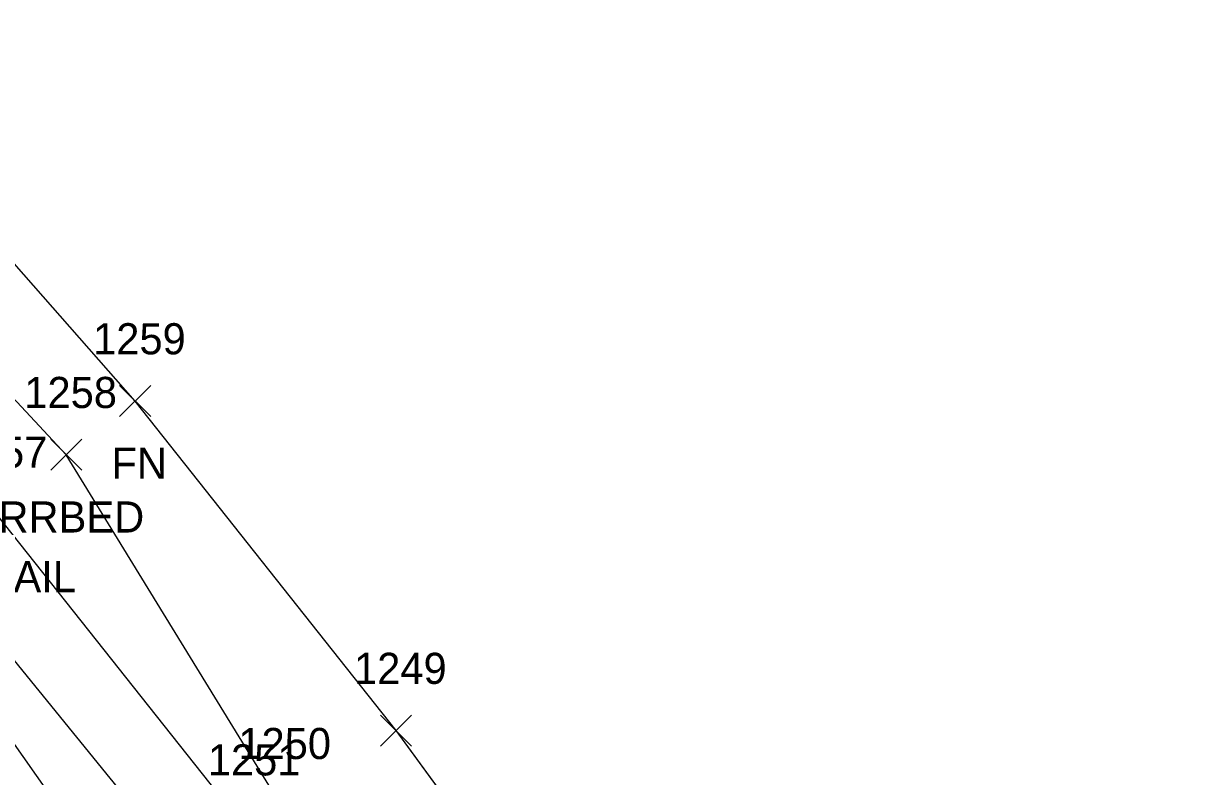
# Model space of a CAD drawing. Extents: x 1715662 to 1717487, y 887396 to 890004.
# Drawn here: x 1716350.8 to 1716426.1, y 888350.9 to 888399.3 of the extents above; entities that cross this region are included whole.
import ezdxf

# ---------------------------------------------------------------- set-up
doc = ezdxf.new("R2010")
doc.units = 0
for name, color, linetype in [('L_A', 7, 'Continuous'), ('L_I', 7, 'Continuous'), ('L_TIC', 7, 'Continuous'), ('LFNC', 7, 'Continuous'), ('LSOGP', 7, 'Continuous'), ('R_A', 7, 'Continuous'), ('R_I', 7, 'Continuous'), ('R_TIC', 7, 'Continuous'), ('RR', 7, 'Continuous'), ('RRB', 7, 'Continuous')]:
    doc.layers.add(name, color=color, linetype=linetype)

msp = doc.modelspace()

# ---------------------------------------------------------------- linework, layer by layer
at = {"layer": 'L_TIC'}
for points in [[(1716357.025, 888374.078), (1716359.025, 888376.078)], [(1716359.025, 888374.078), (1716357.025, 888376.078)], [(1716373.785, 888352.899), (1716375.785, 888354.899)], [(1716375.785, 888352.899), (1716373.785, 888354.899)]]:
    msp.add_lwpolyline(points, dxfattribs=at)
at = {"layer": 'LFNC'}
msp.add_lwpolyline([(1716443.098, 888280.317), (1716420.433, 888282.989), (1716412.543, 888296.715), (1716401.348, 888315.282), (1716386.51, 888337.853), (1716374.785, 888353.899), (1716358.025, 888375.078), (1716341.376, 888394.001), (1716322.754, 888413.454), (1716303.71, 888431.095), (1716282.224, 888449.189), (1716263.808, 888463.099), (1716243.953, 888476.997), (1716231.603, 888485.189), (1716232.765, 888492.604)], dxfattribs=at)
at = {"layer": 'LSOGP'}
msp.add_lwpolyline([(1716469.007, 888433.308), (1716446.639, 888397.104), (1716439.784, 888394.85), (1716438.641, 888388.155), (1716443.71, 888383.152), (1716446.38, 888343.601), (1716442.786, 888319.775), (1716434.149, 888303.757), (1716410.201, 888303.478), (1716401.342, 888315.278), (1716398.071, 888328.134), (1716386.509, 888337.85), (1716374.78, 888353.896), (1716358.023, 888375.075), (1716341.376, 888394), (1716322.749, 888413.449)], dxfattribs=at)
at = {"layer": 'R_TIC'}
for points in [[(1716352.599, 888370.628), (1716354.599, 888372.628)], [(1716354.599, 888370.628), (1716352.599, 888372.628)]]:
    msp.add_lwpolyline(points, dxfattribs=at)
at = {"layer": 'RR'}
for points in [[(1716436.006, 888215.337), (1716430.823, 888230.215), (1716426.348, 888241.635), (1716416.677, 888263.628), (1716410.086, 888277.215), (1716402.001, 888292.439), (1716390.919, 888310.944), (1716376.876, 888331.991), (1716364.819, 888348.018), (1716349.123, 888367.789), (1716332.642, 888386.349), (1716315.07, 888404.654), (1716296.205, 888422.302), (1716278.069, 888437.86), (1716256.9, 888454.27), (1716238.515, 888467.25), (1716223.556, 888476.476), (1716202.573, 888488.846), (1716178.442, 888501.208), (1716153.561, 888512.412), (1716127.616, 888522.226), (1716099.939, 888531.037), (1716073.491, 888537.688), (1716046.147, 888542.834)], [(1716430.72, 888215.397), (1716425.304, 888230.283), (1716421.076, 888241.431), (1716411.445, 888263.23), (1716405.098, 888275.915), (1716397.082, 888291.053), (1716387.606, 888308.839), (1716372.559, 888329.716), (1716360.984, 888345.241), (1716345.129, 888364.699), (1716328.621, 888383.271), (1716311.711, 888401.255), (1716292.491, 888418.83), (1716274.069, 888433.953), (1716254.21, 888450.025), (1716235.796, 888462.901), (1716221.101, 888472.304), (1716200.717, 888484.158), (1716175.893, 888496.909), (1716151.922, 888507.643), (1716125.759, 888517.559), (1716098.568, 888526.188), (1716072.377, 888532.71), (1716045.904, 888537.783)]]:
    msp.add_lwpolyline(points, dxfattribs=at)
at = {"layer": 'RRB'}
for points in [[(1716413.209, 888279.935), (1716405.549, 888293.581), (1716393.281, 888311.771), (1716381.094, 888334.374), (1716367.434, 888349.07), (1716353.599, 888371.628), (1716336.573, 888389.892), (1716318.547, 888409.005), (1716299.812, 888426.157), (1716280.583, 888443.639), (1716260.294, 888458.826), (1716240.844, 888471.367), (1716225.46, 888478.919)], [(1716402.391, 888277.055), (1716395.087, 888289.895), (1716384.284, 888307.273), (1716369.213, 888328.084), (1716357.094, 888343.322), (1716343.151, 888363.152), (1716325.893, 888380.56), (1716309.064, 888397.835), (1716289.633, 888415.582), (1716271.912, 888431.207), (1716252.081, 888447.529), (1716234.746, 888461.341), (1716219.561, 888469.487)]]:
    msp.add_lwpolyline(points, dxfattribs=at)

# ---------------------------------------------------------------- texts
at = {"layer": 'L_A'}
msp.add_text('FN', height=2, dxfattribs=at).set_placement((1716356.505, 888370.078))
at = {"layer": 'L_I'}
for s, p in [('1259', (1716355.324, 888378.078)), ('1249', (1716372.084, 888356.899))]:
    msp.add_text(s, height=2, dxfattribs=at).set_placement(p)
at = {"layer": 'R_A'}
for s, p in [('RRBED', (1716349.245, 888366.628)), ('RRRAIL', (1716344.414, 888362.789))]:
    msp.add_text(s, height=2, dxfattribs=at).set_placement(p)
at = {"layer": 'R_I'}
for s, p in [('1258', (1716350.906, 888374.628)), ('1257', (1716346.43, 888370.789)), ('1250', (1716364.654, 888352.07)), ('1251', (1716362.693, 888351.018))]:
    msp.add_text(s, height=2, dxfattribs=at).set_placement(p)

doc.saveas('drawing.dxf')
